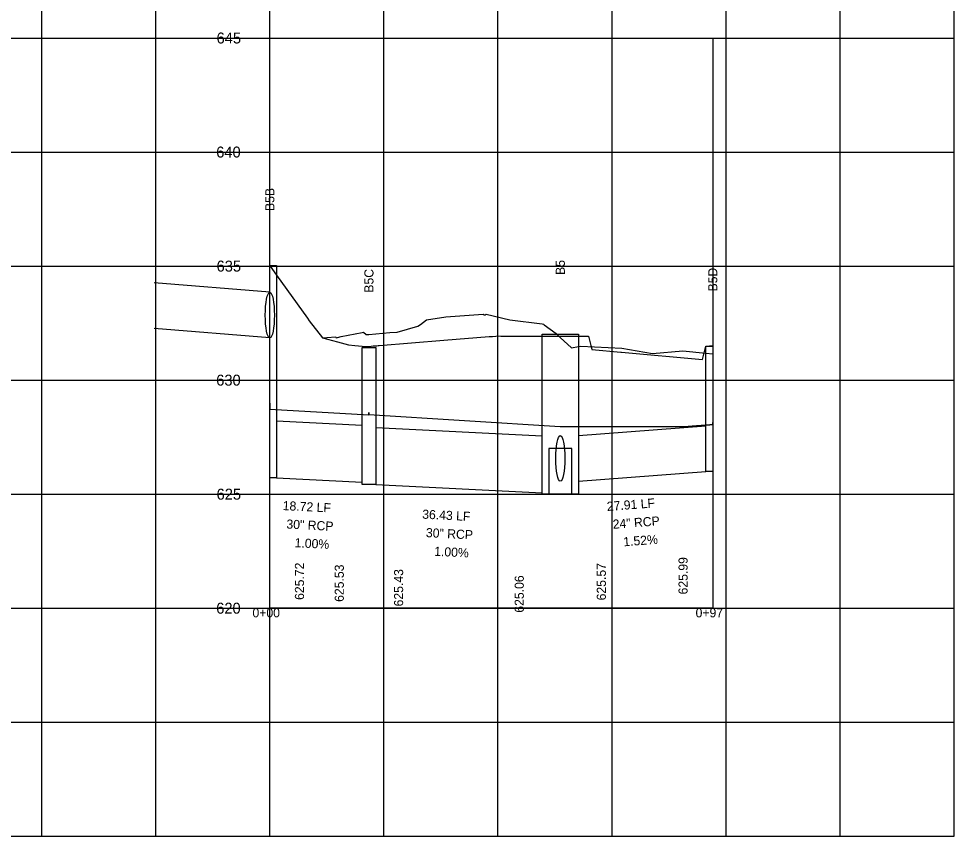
# Model space of a CAD drawing. Extents: x 2254979 to 2278074, y 13790855 to 13792793.
# Drawn here: x 2276869.4 to 2277074.4, y 13792492.6 to 13792671.8 of the extents above; entities that cross this region are included whole.
import ezdxf

# ---------------------------------------------------------------- set-up
doc = ezdxf.new("R2010")
doc.units = 0
for name, color, linetype in [('blank4', 7, 'Continuous'), ('BORD_grid_bottom_major_5int', 7, 'Continuous'), ('D_DRN_PROF_HGL', 7, 'Continuous'), ('D_PROF_1', 7, 'Continuous'), ('D_PROF_NOTES_1', 7, 'Continuous'), ('Default', 7, 'Continuous'), ('Drain_PipeInside', 7, 'Continuous'), ('E_Terrain', 7, 'Continuous'), ('Inlet', 7, 'Continuous'), ('z - Construction', 7, 'Continuous')]:
    doc.layers.add(name, color=color, linetype=linetype)

msp = doc.modelspace()

# ---------------------------------------------------------------- linework, layer by layer
at = {"layer": 'blank4'}
msp.add_lwpolyline([(2276924.4, 13792542.6), (2276924.4, 13792667.6), (2277021.47, 13792667.6), (2277021.47, 13792542.6)], close=True, dxfattribs=at)
at = {"layer": 'BORD_grid_bottom_major_5int'}
for p, q in [((2276874.4, 13792492.6), (2276874.4, 13792792.6)), ((2276899.4, 13792492.6), (2276899.4, 13792792.6)), ((2276924.4, 13792492.6), (2276924.4, 13792792.6)), ((2276949.4, 13792492.6), (2276949.4, 13792792.6)), ((2276974.4, 13792492.6), (2276974.4, 13792792.6)), ((2276999.4, 13792492.6), (2276999.4, 13792792.6)), ((2277024.4, 13792492.6), (2277024.4, 13792792.6)), ((2277049.4, 13792492.6), (2277049.4, 13792792.6)), ((2277074.4, 13792492.6), (2277074.4, 13792792.6)), ((2276749.4, 13792667.6), (2277074.4, 13792667.6)), ((2276749.4, 13792642.6), (2277074.4, 13792642.6)), ((2276749.4, 13792617.6), (2277074.4, 13792617.6)), ((2276749.4, 13792592.6), (2277074.4, 13792592.6)), ((2276749.4, 13792567.6), (2277074.4, 13792567.6)), ((2276749.4, 13792542.6), (2277074.4, 13792542.6)), ((2276749.4, 13792517.6), (2277074.4, 13792517.6)), ((2276749.4, 13792492.6), (2277074.4, 13792492.6))]:
    msp.add_line(p, q, dxfattribs=at)
at = {"layer": 'D_DRN_PROF_HGL'}
for p, q in [((2276946.12, 13792584.99), (2276946.12, 13792585.54)), ((2276988.06, 13792582.45), (2276988.06, 13792582.45))]:
    msp.add_line(p, q, dxfattribs=at)
for points in [[(2276924.4, 13792587.55), (2276924.4, 13792586.25), (2276946.12, 13792584.99)], [(2276946.12, 13792585.54), (2276946.12, 13792585.03), (2276988.06, 13792582.45)], [(2276988.06, 13792582.45), (2276988.12, 13792582.45), (2276988.19, 13792582.45), (2276988.25, 13792582.45), (2276988.32, 13792582.45), (2276988.39, 13792582.45), (2276988.45, 13792582.45), (2276988.52, 13792582.45), (2276988.59, 13792582.45), (2276988.65, 13792582.45), (2276988.72, 13792582.45), (2276988.79, 13792582.45), (2276988.85, 13792582.45), (2276988.92, 13792582.45), (2276988.98, 13792582.45), (2276989.05, 13792582.45), (2276989.12, 13792582.45), (2276989.18, 13792582.45), (2276989.25, 13792582.45), (2276989.32, 13792582.46), (2276989.38, 13792582.46), (2276989.45, 13792582.46), (2276989.52, 13792582.46), (2276989.58, 13792582.46), (2276989.65, 13792582.46), (2276989.71, 13792582.46), (2276989.78, 13792582.46), (2276989.85, 13792582.46), (2276989.91, 13792582.46), (2276989.98, 13792582.46), (2276990.05, 13792582.46), (2276990.11, 13792582.46), (2276990.18, 13792582.46), (2276990.24, 13792582.46), (2276990.31, 13792582.46), (2276990.38, 13792582.46), (2276990.44, 13792582.46), (2276990.51, 13792582.46), (2276990.58, 13792582.46), (2276990.64, 13792582.46), (2276990.71, 13792582.46), (2276990.78, 13792582.46), (2276990.84, 13792582.46), (2276990.91, 13792582.46), (2276990.97, 13792582.46), (2276991.04, 13792582.46), (2276991.11, 13792582.46), (2276991.17, 13792582.46), (2276991.24, 13792582.46), (2276991.31, 13792582.46), (2276991.37, 13792582.46), (2276991.44, 13792582.46), (2276991.51, 13792582.46), (2276991.57, 13792582.46), (2276991.64, 13792582.46), (2276991.7, 13792582.46), (2276991.77, 13792582.46), (2276991.84, 13792582.46), (2276991.9, 13792582.46), (2276991.97, 13792582.46), (2276992.04, 13792582.46), (2276992.1, 13792582.46), (2276992.17, 13792582.46), (2276992.24, 13792582.46), (2276992.3, 13792582.46), (2276992.37, 13792582.46), (2276992.43, 13792582.46), (2276992.5, 13792582.46), (2276992.57, 13792582.46), (2276992.63, 13792582.46), (2276992.7, 13792582.46), (2276992.77, 13792582.46), (2276992.83, 13792582.46), (2276992.9, 13792582.46), (2276992.96, 13792582.46), (2276993.03, 13792582.46), (2276993.1, 13792582.46), (2276993.16, 13792582.46), (2276993.23, 13792582.46), (2276993.3, 13792582.46), (2276993.36, 13792582.46), (2276993.43, 13792582.46), (2276993.5, 13792582.46), (2276993.56, 13792582.46), (2276993.63, 13792582.46), (2276993.69, 13792582.46), (2276993.76, 13792582.46), (2276993.83, 13792582.46), (2276993.89, 13792582.46), (2276993.96, 13792582.46), (2276994.03, 13792582.46), (2276994.09, 13792582.46), (2276994.16, 13792582.46), (2276994.23, 13792582.46), (2276994.29, 13792582.46), (2276994.36, 13792582.46), (2276994.42, 13792582.46), (2276994.49, 13792582.46), (2276994.56, 13792582.46), (2276994.62, 13792582.46), (2276994.69, 13792582.46), (2276994.76, 13792582.46), (2276994.82, 13792582.46), (2276994.89, 13792582.46), (2276994.96, 13792582.46), (2276995.02, 13792582.46), (2276995.09, 13792582.46), (2276995.15, 13792582.46), (2276995.22, 13792582.46), (2276995.29, 13792582.46), (2276995.35, 13792582.46), (2276995.42, 13792582.46), (2276995.49, 13792582.46), (2276995.55, 13792582.46), (2276995.62, 13792582.46), (2276995.69, 13792582.46), (2276995.75, 13792582.46), (2276995.82, 13792582.46), (2276995.88, 13792582.46), (2276995.95, 13792582.46), (2276996.02, 13792582.46), (2276996.08, 13792582.46), (2276996.15, 13792582.46), (2276996.22, 13792582.46), (2276996.28, 13792582.46), (2276996.35, 13792582.46), (2276996.41, 13792582.46), (2276996.48, 13792582.46), (2276996.55, 13792582.46), (2276996.61, 13792582.46), (2276996.68, 13792582.46), (2276996.75, 13792582.46), (2276996.81, 13792582.46), (2276996.88, 13792582.46), (2276996.95, 13792582.46), (2276997.01, 13792582.46), (2276997.08, 13792582.46), (2276997.14, 13792582.46), (2276997.21, 13792582.46), (2276997.28, 13792582.46), (2276997.34, 13792582.46), (2276997.41, 13792582.46), (2276997.48, 13792582.46), (2276997.54, 13792582.46), (2276997.61, 13792582.46), (2276997.68, 13792582.46), (2276997.74, 13792582.46), (2276997.81, 13792582.46), (2276997.87, 13792582.46), (2276997.94, 13792582.46), (2276998.01, 13792582.46), (2276998.07, 13792582.46), (2276998.14, 13792582.46), (2276998.21, 13792582.46), (2276998.27, 13792582.46), (2276998.34, 13792582.46), (2276998.41, 13792582.46), (2276998.47, 13792582.46), (2276998.54, 13792582.46), (2276998.6, 13792582.46), (2276998.67, 13792582.46), (2276998.74, 13792582.46), (2276998.8, 13792582.46), (2276998.87, 13792582.46), (2276998.94, 13792582.46), (2276999, 13792582.46), (2276999.07, 13792582.46), (2276999.14, 13792582.46), (2276999.2, 13792582.46), (2276999.27, 13792582.46), (2276999.33, 13792582.46), (2276999.4, 13792582.46), (2276999.47, 13792582.46), (2276999.53, 13792582.46), (2276999.6, 13792582.46), (2276999.67, 13792582.46), (2276999.73, 13792582.46), (2276999.8, 13792582.46), (2276999.86, 13792582.46), (2276999.93, 13792582.46), (2277000, 13792582.46), (2277000.06, 13792582.46), (2277000.13, 13792582.46), (2277000.2, 13792582.46), (2277000.26, 13792582.46), (2277000.33, 13792582.46), (2277000.4, 13792582.46), (2277000.46, 13792582.46), (2277000.53, 13792582.46), (2277000.59, 13792582.46), (2277000.66, 13792582.46), (2277000.73, 13792582.46), (2277000.79, 13792582.46), (2277000.86, 13792582.46), (2277000.93, 13792582.46), (2277000.99, 13792582.46), (2277001.06, 13792582.46), (2277001.13, 13792582.46), (2277001.19, 13792582.46), (2277001.26, 13792582.46), (2277001.32, 13792582.46), (2277001.39, 13792582.46), (2277001.46, 13792582.46), (2277001.52, 13792582.46), (2277001.59, 13792582.46), (2277001.66, 13792582.46), (2277001.72, 13792582.46), (2277001.79, 13792582.46), (2277001.86, 13792582.46), (2277001.92, 13792582.46), (2277001.99, 13792582.46), (2277002.05, 13792582.46), (2277002.12, 13792582.46), (2277002.19, 13792582.46), (2277002.25, 13792582.46), (2277002.32, 13792582.46), (2277002.39, 13792582.46), (2277002.45, 13792582.46), (2277002.52, 13792582.46), (2277002.59, 13792582.46), (2277002.65, 13792582.46), (2277002.72, 13792582.46), (2277002.78, 13792582.46), (2277002.85, 13792582.46), (2277002.92, 13792582.46), (2277002.98, 13792582.46), (2277003.05, 13792582.46), (2277003.12, 13792582.46), (2277003.18, 13792582.46), (2277003.25, 13792582.46), (2277003.31, 13792582.46), (2277003.38, 13792582.46), (2277003.45, 13792582.46), (2277003.51, 13792582.46), (2277003.58, 13792582.46), (2277003.65, 13792582.46), (2277003.71, 13792582.46), (2277003.78, 13792582.46), (2277003.85, 13792582.46), (2277003.91, 13792582.46), (2277003.98, 13792582.46), (2277004.04, 13792582.46), (2277004.11, 13792582.46), (2277004.18, 13792582.46), (2277004.24, 13792582.46), (2277004.31, 13792582.46), (2277004.38, 13792582.46), (2277004.44, 13792582.46), (2277004.51, 13792582.46), (2277004.58, 13792582.46), (2277004.64, 13792582.46), (2277004.71, 13792582.46), (2277004.77, 13792582.46), (2277004.84, 13792582.46), (2277004.91, 13792582.46), (2277004.97, 13792582.46), (2277005.04, 13792582.46), (2277005.11, 13792582.46), (2277005.17, 13792582.46), (2277005.24, 13792582.46), (2277005.31, 13792582.46), (2277005.37, 13792582.46), (2277005.44, 13792582.46), (2277005.5, 13792582.46), (2277005.57, 13792582.46), (2277005.64, 13792582.46), (2277005.7, 13792582.46), (2277005.77, 13792582.46), (2277005.84, 13792582.46), (2277005.9, 13792582.46), (2277005.97, 13792582.46), (2277006.03, 13792582.46), (2277006.1, 13792582.46), (2277006.17, 13792582.46), (2277006.23, 13792582.46), (2277006.3, 13792582.46), (2277006.37, 13792582.46), (2277006.43, 13792582.46), (2277006.5, 13792582.46), (2277006.57, 13792582.46), (2277006.63, 13792582.46), (2277006.7, 13792582.46), (2277006.76, 13792582.46), (2277006.83, 13792582.46), (2277006.9, 13792582.46), (2277006.96, 13792582.46), (2277007.03, 13792582.46), (2277007.1, 13792582.46), (2277007.16, 13792582.46), (2277007.23, 13792582.46), (2277007.3, 13792582.46), (2277007.36, 13792582.46), (2277007.43, 13792582.46), (2277007.49, 13792582.46), (2277007.56, 13792582.46), (2277007.63, 13792582.46), (2277007.69, 13792582.46), (2277007.76, 13792582.46), (2277007.83, 13792582.46), (2277007.89, 13792582.46), (2277007.96, 13792582.46), (2277008.03, 13792582.46), (2277008.09, 13792582.46), (2277008.16, 13792582.46), (2277008.22, 13792582.46), (2277008.29, 13792582.46), (2277008.36, 13792582.46), (2277008.42, 13792582.46), (2277008.49, 13792582.46), (2277008.56, 13792582.46), (2277008.62, 13792582.46), (2277008.69, 13792582.46), (2277008.76, 13792582.46), (2277008.82, 13792582.46), (2277008.89, 13792582.46), (2277008.95, 13792582.46), (2277009.02, 13792582.46), (2277009.09, 13792582.46), (2277009.15, 13792582.46), (2277009.22, 13792582.46), (2277009.29, 13792582.46), (2277009.35, 13792582.46), (2277009.42, 13792582.46), (2277009.48, 13792582.46), (2277009.55, 13792582.46), (2277009.62, 13792582.46), (2277009.68, 13792582.46), (2277009.75, 13792582.46), (2277009.82, 13792582.46), (2277009.88, 13792582.46), (2277009.95, 13792582.46), (2277010.02, 13792582.46), (2277010.08, 13792582.46), (2277010.15, 13792582.46), (2277010.21, 13792582.46), (2277010.28, 13792582.46), (2277010.35, 13792582.46), (2277010.41, 13792582.46), (2277010.48, 13792582.46), (2277010.55, 13792582.46), (2277010.61, 13792582.46), (2277010.68, 13792582.46), (2277010.75, 13792582.46), (2277010.81, 13792582.46), (2277010.88, 13792582.46), (2277010.94, 13792582.46), (2277011.01, 13792582.46), (2277011.08, 13792582.46), (2277011.14, 13792582.46), (2277011.21, 13792582.46), (2277011.28, 13792582.46), (2277011.34, 13792582.46), (2277011.41, 13792582.46), (2277011.48, 13792582.46), (2277011.54, 13792582.46), (2277011.61, 13792582.46), (2277011.67, 13792582.46), (2277011.74, 13792582.46), (2277011.81, 13792582.46), (2277011.87, 13792582.46), (2277011.94, 13792582.46), (2277012.01, 13792582.46), (2277012.07, 13792582.46), (2277012.14, 13792582.46), (2277012.21, 13792582.46), (2277012.27, 13792582.46), (2277012.34, 13792582.46), (2277012.4, 13792582.46), (2277012.47, 13792582.46), (2277012.54, 13792582.46), (2277012.6, 13792582.46), (2277012.67, 13792582.46), (2277012.74, 13792582.46), (2277012.8, 13792582.46), (2277012.87, 13792582.46), (2277012.93, 13792582.46), (2277013, 13792582.46), (2277013.07, 13792582.46), (2277013.13, 13792582.46), (2277013.2, 13792582.46), (2277013.27, 13792582.47), (2277013.33, 13792582.47), (2277013.4, 13792582.47), (2277013.47, 13792582.47), (2277013.53, 13792582.47), (2277013.6, 13792582.47), (2277013.66, 13792582.47), (2277013.73, 13792582.47), (2277013.8, 13792582.47), (2277013.86, 13792582.47), (2277013.93, 13792582.47), (2277014, 13792582.47), (2277014.06, 13792582.47), (2277014.13, 13792582.47), (2277014.2, 13792582.47), (2277014.26, 13792582.47), (2277014.33, 13792582.47), (2277014.39, 13792582.47), (2277014.46, 13792582.47), (2277014.53, 13792582.47), (2277014.59, 13792582.47), (2277014.66, 13792582.47), (2277014.73, 13792582.47), (2277014.79, 13792582.47), (2277014.86, 13792582.47), (2277014.93, 13792582.47), (2277014.99, 13792582.47), (2277015.06, 13792582.47), (2277015.12, 13792582.47), (2277015.19, 13792582.47), (2277015.26, 13792582.47), (2277015.32, 13792582.47), (2277015.39, 13792582.47), (2277015.46, 13792582.47), (2277015.52, 13792582.47), (2277015.59, 13792582.47), (2277015.65, 13792582.47), (2277015.72, 13792582.47), (2277015.79, 13792582.47), (2277015.85, 13792582.47), (2277015.92, 13792582.47), (2277015.99, 13792582.47), (2277016.05, 13792582.47), (2277016.12, 13792582.48), (2277016.18, 13792582.48), (2277016.25, 13792582.49), (2277016.32, 13792582.49), (2277016.38, 13792582.5), (2277016.45, 13792582.5), (2277016.51, 13792582.51), (2277016.58, 13792582.51), (2277016.65, 13792582.52), (2277016.71, 13792582.52), (2277016.78, 13792582.53), (2277016.85, 13792582.53), (2277016.91, 13792582.54), (2277016.98, 13792582.54), (2277017.04, 13792582.55), (2277017.11, 13792582.55), (2277017.18, 13792582.56), (2277017.24, 13792582.56), (2277017.31, 13792582.57), (2277017.37, 13792582.57), (2277017.44, 13792582.58), (2277017.51, 13792582.58), (2277017.57, 13792582.59), (2277017.64, 13792582.59), (2277017.71, 13792582.6), (2277017.77, 13792582.6), (2277017.84, 13792582.61), (2277017.9, 13792582.61), (2277017.97, 13792582.62), (2277018.04, 13792582.62), (2277018.1, 13792582.63), (2277018.17, 13792582.63), (2277018.23, 13792582.64), (2277018.3, 13792582.64), (2277018.37, 13792582.65), (2277018.43, 13792582.65), (2277018.5, 13792582.66), (2277018.56, 13792582.66), (2277018.63, 13792582.67), (2277018.7, 13792582.67), (2277018.76, 13792582.68), (2277018.83, 13792582.68), (2277018.89, 13792582.69), (2277018.96, 13792582.69), (2277019.03, 13792582.7), (2277019.09, 13792582.7), (2277019.16, 13792582.71), (2277019.22, 13792582.71), (2277019.29, 13792582.72), (2277019.36, 13792582.72), (2277019.42, 13792582.73), (2277019.49, 13792582.73), (2277019.56, 13792582.74), (2277019.62, 13792582.74), (2277019.69, 13792582.75), (2277019.75, 13792582.75), (2277019.82, 13792582.76), (2277019.89, 13792582.76), (2277019.95, 13792582.77), (2277020.02, 13792582.77), (2277020.08, 13792582.78), (2277020.15, 13792582.78), (2277020.22, 13792582.79), (2277020.28, 13792582.79), (2277020.35, 13792582.8), (2277020.41, 13792582.8), (2277020.48, 13792582.81), (2277020.55, 13792582.81), (2277020.61, 13792582.82), (2277020.68, 13792582.82), (2277020.74, 13792582.83), (2277020.81, 13792582.83), (2277020.88, 13792582.84), (2277020.94, 13792582.84), (2277021.01, 13792582.85), (2277021.07, 13792582.85), (2277021.14, 13792582.86), (2277021.21, 13792582.86), (2277021.27, 13792582.87), (2277021.34, 13792582.87), (2277021.4, 13792582.88), (2277021.47, 13792582.88), (2277021.47, 13792583.34)]]:
    msp.add_lwpolyline(points, dxfattribs=at)
at = {"layer": 'D_PROF_1'}
for p, q in [((2276924.4, 13792611.85), (2276899.05, 13792613.92)), ((2276924.4, 13792601.85), (2276899.05, 13792603.92))]:
    msp.add_line(p, q, dxfattribs=at)
msp.add_lwpolyline([(2276935.94, 13792601.87), (2276939.26, 13792601.01), (2276941.63, 13792600.31), (2276943.05, 13792600.18), (2276944.62, 13792600.04), (2276944.62, 13792600.04), (2276945.44, 13792599.96), (2276945.93, 13792600), (2276946.12, 13792600.01), (2276946.12, 13792600.01), (2276946.63, 13792600.05), (2276947.05, 13792600.09), (2276947.62, 13792600.13), (2276947.62, 13792600.13), (2276947.63, 13792600.13), (2276947.85, 13792600.15), (2276948.15, 13792600.17), (2276948.25, 13792600.18), (2276948.25, 13792600.18), (2276948.38, 13792600.19), (2276962.5, 13792601.33), (2276972.48, 13792602.13), (2276972.64, 13792602.15), (2276972.71, 13792602.15), (2276973.07, 13792602.18), (2276973.23, 13792602.19), (2276973.94, 13792602.25), (2276974.23, 13792602.28), (2276975.05, 13792602.27), (2276975.38, 13792602.27), (2276984.06, 13792602.26), (2276984.06, 13792602.26), (2276988.06, 13792602.24), (2276988.06, 13792602.24), (2276990.64, 13792602.22), (2276992.06, 13792602.21), (2276992.06, 13792602.21), (2276994.23, 13792602.21), (2276994.68, 13792600.47), (2276994.75, 13792600.19), (2276994.95, 13792599.42), (2276994.98, 13792599.31), (2277001.33, 13792598.74), (2277001.36, 13792598.73), (2277001.47, 13792598.72), (2277019.21, 13792597.13), (2277019.44, 13792597.99), (2277019.44, 13792598.02), (2277019.97, 13792600.05), (2277019.97, 13792600.05), (2277019.97, 13792600.05), (2277021.47, 13792600.2)], dxfattribs=at)
at = {"layer": 'Drain_PipeInside'}
for p, q in [((2276925.9, 13792583.68), (2276944.62, 13792582.74)), ((2276947.62, 13792582.24), (2276984.06, 13792580.42)), ((2276992.06, 13792580.43), (2277019.97, 13792582.55)), ((2276925.9, 13792571.18), (2276944.62, 13792570.24)), ((2276992.06, 13792570.43), (2277019.97, 13792572.55)), ((2276947.62, 13792569.74), (2276984.06, 13792567.92))]:
    msp.add_line(p, q, dxfattribs=at)
msp.add_lwpolyline([(2276985.56, 13792567.6), (2276990.56, 13792567.6), (2276990.56, 13792577.6), (2276985.56, 13792577.6)], close=True, dxfattribs=at)
for centre in [(2276924.4, 13792606.85), (2276988.06, 13792575.43)]:
    msp.add_ellipse(centre, major_axis=(0, 5), ratio=0.2, dxfattribs=at)
at = {"layer": 'E_Terrain'}
msp.add_lwpolyline([(2276924.47, 13792617.6), (2276925.9, 13792615.58), (2276925.9, 13792615.58), (2276932.66, 13792606.15), (2276933.02, 13792605.6), (2276935.94, 13792601.87), (2276936.89, 13792601.96), (2276938.86, 13792602.09), (2276938.95, 13792601.84), (2276939.21, 13792601.94), (2276940.01, 13792602.14), (2276944.62, 13792603.07), (2276944.62, 13792603.07), (2276944.92, 13792603.12), (2276945.48, 13792602.57), (2276946.12, 13792602.63), (2276946.12, 13792602.63), (2276947.62, 13792602.76), (2276947.62, 13792602.76), (2276950.7, 13792603.03), (2276952.29, 13792603.12), (2276956.85, 13792604.45), (2276957.39, 13792604.83), (2276958.72, 13792605.82), (2276962.95, 13792606.51), (2276971.14, 13792607.09), (2276971.4, 13792606.95), (2276971.62, 13792606.95), (2276971.83, 13792607.09), (2276977.02, 13792605.82), (2276984.06, 13792604.93), (2276984.06, 13792604.93), (2276984.39, 13792604.88), (2276984.53, 13792604.72), (2276987.17, 13792602.81), (2276988.06, 13792601.97), (2276988.06, 13792601.97), (2276990.5, 13792599.66), (2276992.06, 13792599.95), (2276992.06, 13792599.95), (2276992.54, 13792600.05), (2277001.55, 13792599.59), (2277008.23, 13792598.43), (2277014.94, 13792598.99), (2277019.97, 13792598.5), (2277019.97, 13792598.5), (2277021.47, 13792598.34)], dxfattribs=at)
at = {"layer": 'Inlet'}
for points in [[(2276924.4, 13792617.7), (2276925.9, 13792617.7), (2276925.9, 13792571.18), (2276924.4, 13792571.18)], [(2276984.06, 13792602.65), (2276992.06, 13792602.65), (2276992.06, 13792567.6), (2276984.06, 13792567.6)], [(2276944.62, 13792599.75), (2276947.62, 13792599.75), (2276947.62, 13792569.74), (2276944.62, 13792569.74)], [(2277019.97, 13792600.05), (2277021.47, 13792600.05), (2277021.47, 13792572.55), (2277019.97, 13792572.55)]]:
    msp.add_lwpolyline(points, close=True, dxfattribs=at)
at = {"layer": 'z - Construction'}
for p, q in [((2276924.4, 13792642.6), (2277021.47, 13792642.6)), ((2276924.4, 13792617.6), (2277021.47, 13792617.6)), ((2276924.4, 13792592.6), (2277021.47, 13792592.6)), ((2276924.4, 13792567.6), (2277021.47, 13792567.6))]:
    msp.add_line(p, q, dxfattribs=at)

# ---------------------------------------------------------------- texts
at = {"layer": 'D_PROF_NOTES_1'}
for s, rotation, p in [('B5B', 90, (2276925.4, 13792629.67)), ('B5', 90, (2276989.06, 13792615.67)), ('B5C', 90, (2276947.12, 13792611.77)), ('B5D', 90, (2277022.47, 13792612.04)), ('27.91 LF', 4.3333, (2276998.33, 13792563.91)), ('18.72 LF', 357.1376, (2276927.19, 13792564.12)), ('36.43 LF', 357.1376, (2276957.76, 13792562.24)), ('24" RCP', 4.3333, (2276999.63, 13792560)), ('30" RCP', 357.1376, (2276928, 13792560.07)), ('30" RCP', 357.1376, (2276958.57, 13792558.19)), ('1.52%', 4.3333, (2277001.94, 13792556.16)), ('1.00%', 357.1376, (2276929.8, 13792555.98)), ('1.00%', 357.1376, (2276960.38, 13792554.1)), ('625.72', 90, (2276931.9, 13792544.42)), ('625.57', 90, (2276998.05, 13792544.32)), ('625.99', 90, (2277015.97, 13792545.62)), ('625.53', 90, (2276940.62, 13792543.99)), ('625.43', 90, (2276953.62, 13792542.99)), ('625.06', 90, (2276980.06, 13792541.62))]:
    msp.add_text(s, height=2, rotation=rotation, dxfattribs=at).set_placement(p)
at = {"layer": 'Default'}
for s, height, p in [('645', 2.4, (2276912.74, 13792666.4)), ('640', 2.4, (2276912.66, 13792641.4)), ('635', 2.4, (2276912.74, 13792616.4)), ('630', 2.4, (2276912.66, 13792591.4)), ('625', 2.4, (2276912.74, 13792566.4)), ('620', 2.4, (2276912.66, 13792541.4)), ('0+00', 2, (2276920.6, 13792540.6)), ('0+97', 2, (2277017.71, 13792540.6))]:
    msp.add_text(s, height=height, dxfattribs=at).set_placement(p)

doc.saveas('drawing.dxf')
